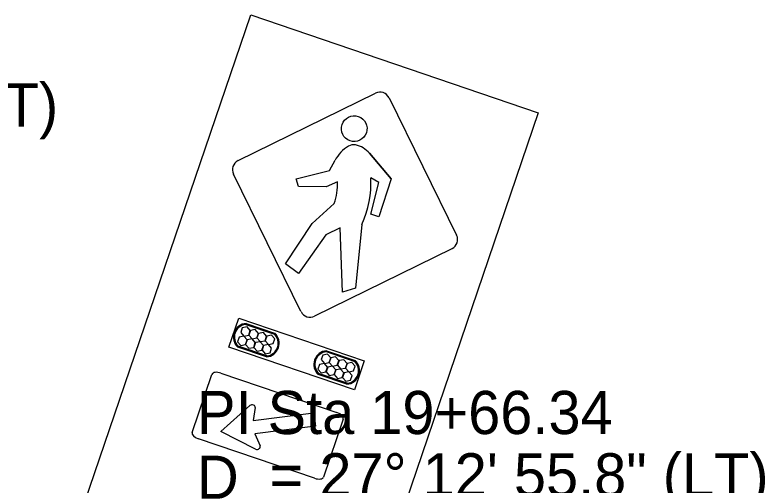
# Model space of a CAD drawing. Extents: x 902965 to 1126554, y 597041 to 686906.
# Drawn here: x 928783.5 to 928905.1, y 686035.7 to 686112 of the extents above; entities that cross this region are included whole.
import ezdxf

# ---------------------------------------------------------------- set-up
doc = ezdxf.new("R2010")
doc.units = 0
for name, color, linetype in [('CTL North Arrow CELL', 7, 'Continuous'), ('Default', 7, 'Continuous'), ('Exist Horizontal Alignment Curve and Spiral Data', 7, 'Continuous'), ('Exist Utilities Water Meter CELL', 7, 'Continuous'), ('WS W11-2 CELL', 7, 'Continuous'), ('WS W16-7p CELL', 7, 'Continuous')]:
    doc.layers.add(name, color=color, linetype=linetype)

msp = doc.modelspace()

# ---------------------------------------------------------------- linework, layer by layer
at = {"layer": 'CTL North Arrow CELL'}
for p, q in [((928785.5, 686005.71), (928821.71, 686111.98)), ((928821.71, 686111.98), (928868.34, 686096.09)), ((928868.34, 686096.09), (928832.13, 685989.82))]:
    msp.add_line(p, q, dxfattribs=at)
at = {"layer": 'Default'}
for points in [[(928838.54, 686051.18), (928818.17, 686058.12), (928819.77, 686062.81), (928840.13, 686055.87)], [(928821.64, 686060.8), (928821.12, 686061.4), (928820.34, 686061.25), (928820.08, 686060.5), (928820.6, 686059.89), (928821.39, 686060.05)], [(928822.96, 686060.34), (928822.44, 686060.94), (928821.66, 686060.79), (928821.4, 686060.04), (928821.92, 686059.44), (928822.71, 686059.59)], [(928824.29, 686059.89), (928823.76, 686060.49), (928822.98, 686060.34), (928822.72, 686059.59), (928823.25, 686058.99), (928824.03, 686059.14)], [(928821.13, 686059.28), (928820.6, 686059.88), (928819.82, 686059.73), (928819.56, 686058.97), (928820.09, 686058.37), (928820.87, 686058.53)], [(928822.45, 686058.83), (928821.93, 686059.43), (928821.14, 686059.27), (928820.88, 686058.52), (928821.41, 686057.92), (928822.19, 686058.07)], [(928825.61, 686059.45), (928825.09, 686060.05), (928824.31, 686059.9), (928824.05, 686059.14), (928824.57, 686058.54), (928825.36, 686058.7)], [(928823.77, 686058.38), (928823.25, 686058.98), (928822.47, 686058.83), (928822.21, 686058.07), (928822.73, 686057.47), (928823.52, 686057.63)], [(928825.1, 686057.93), (928824.58, 686058.53), (928823.8, 686058.38), (928823.54, 686057.62), (928824.06, 686057.02), (928824.84, 686057.18)], [(928834.69, 686056.37), (928834.16, 686056.97), (928833.38, 686056.82), (928833.12, 686056.07), (928833.65, 686055.46), (928834.43, 686055.62)], [(928836.01, 686055.91), (928835.48, 686056.51), (928834.7, 686056.36), (928834.44, 686055.61), (928834.97, 686055.01), (928835.75, 686055.16)], [(928837.33, 686055.46), (928836.81, 686056.06), (928836.03, 686055.91), (928835.77, 686055.16), (928836.29, 686054.56), (928837.07, 686054.71)], [(928838.66, 686055.02), (928838.13, 686055.62), (928837.35, 686055.47), (928837.09, 686054.71), (928837.62, 686054.11), (928838.4, 686054.27)], [(928834.17, 686054.85), (928833.65, 686055.45), (928832.86, 686055.3), (928832.61, 686054.54), (928833.13, 686053.94), (928833.91, 686054.1)], [(928835.49, 686054.4), (928834.97, 686055), (928834.19, 686054.85), (928833.93, 686054.09), (928834.45, 686053.49), (928835.23, 686053.64)], [(928836.82, 686053.95), (928836.29, 686054.55), (928835.51, 686054.4), (928835.25, 686053.65), (928835.78, 686053.04), (928836.56, 686053.2)], [(928838.15, 686053.5), (928837.62, 686054.1), (928836.84, 686053.95), (928836.58, 686053.19), (928837.11, 686052.59), (928837.89, 686052.75)]]:
    msp.add_lwpolyline(points, close=True, dxfattribs=at)
at = {"layer": 'Exist Utilities Water Meter CELL'}
for p, q in [((928822.62, 686059.23), (928822.62, 686059.23)), ((928835.66, 686054.8), (928835.66, 686054.8))]:
    msp.add_line(p, q, dxfattribs=at)
for points in [[(928820.91, 686061.8), (928825.54, 686060.22)], [(928820.96, 686061.95), (928825.59, 686060.38)], [(928824.27, 686056.51), (928819.62, 686058.1)], [(928824.33, 686056.67), (928819.67, 686058.26)], [(928833.95, 686057.37), (928838.58, 686055.79)], [(928834, 686057.52), (928838.63, 686055.95)], [(928837.32, 686052.08), (928832.66, 686053.67)], [(928837.37, 686052.24), (928832.71, 686053.83)]]:
    msp.add_lwpolyline(points, dxfattribs=at)
for centre, radius, start, end in [((928821.13, 686059.73), 2.23, 94.3617, 227.1631), ((928821.14, 686059.73), 2.08, 96.4846, 224.9661), ((928824.09, 686058.73), 2.23, 274.832, 47.4921), ((928824.1, 686058.73), 2.07, 276.3109, 46.0565), ((928834.17, 686055.3), 2.23, 94.3617, 227.1631), ((928834.19, 686055.3), 2.08, 96.4846, 224.9661), ((928837.13, 686054.3), 2.23, 274.832, 47.4921), ((928837.14, 686054.3), 2.07, 276.3109, 46.0565)]:
    msp.add_arc(centre, radius, start, end, dxfattribs=at)
at = {"layer": 'WS W11-2 CELL'}
for p, q in [((928834.5, 686086.77), (928835.39, 686088.41)), ((928840.98, 686089.55), (928844.51, 686085.39)), ((928844.51, 686085.39), (928840.98, 686089.55)), ((928840.98, 686089.55), (928844.51, 686085.39)), ((928829.1, 686085.38), (928834.5, 686086.77)), ((928829.46, 686084.17), (928829.1, 686085.38)), ((928835.78, 686084.92), (928833.97, 686084.12)), ((928842.51, 686084.79), (928841.17, 686085.57)), ((928841.21, 686079.65), (928842.51, 686084.79)), ((928844.51, 686085.39), (928842.47, 686079.22)), ((928833.97, 686084.12), (928829.46, 686084.17)), ((928831.7, 686078.14), (928835.26, 686081.42)), ((928842.47, 686079.22), (928841.21, 686079.65)), ((928827.36, 686071.59), (928831.7, 686078.14)), ((928839.72, 686078.02), (928838.72, 686067.66)), ((928833.9, 686076.3), (928829.46, 686070.04)), ((928836.22, 686077.43), (928833.9, 686076.3)), ((928836.59, 686067.04), (928836.22, 686077.43)), ((928854.35, 686074.07), (928832.06, 686063.11)), ((928854.35, 686074.07), (928832.06, 686063.11)), ((928829.46, 686070.04), (928827.36, 686071.59)), ((928838.72, 686067.66), (928836.59, 686067.04))]:
    msp.add_line(p, q, dxfattribs=at)
for points in [[(928819.65, 686088.35), (928841.94, 686099.31)], [(928844.14, 686098.56), (928855.1, 686076.27)], [(928829.86, 686063.86), (928818.9, 686086.15)]]:
    msp.add_lwpolyline(points, dxfattribs=at)
for centre, major_axis, start_param, end_param in [((928842.67, 686097.84), (0.53, 1.55), 6.283072, 7.068583), ((928842.67, 686097.84), (0.53, 1.55), 5.49756, 6.283072), ((928838.38, 686089.36), (-0.51, -1.49), 3.261682, 4.017186), ((928837.86, 686086.89), (1.32, 3.88), 5.744678, 6.403274), ((928840.7, 686085.56), (-1.95, -5.71), 4.017186, 4.547553), ((928820.37, 686086.88), (0.53, 1.55), 0.785398, 2.356194), ((928825.65, 686084.64), (3.27, 9.6), 4.717416, 5.067864), ((928825.65, 686084.64), (5.02, 14.72), 4.60131, 5.100443), ((928853.63, 686075.55), (0.53, 1.55), 3.926991, 5.497787), ((928831.34, 686064.58), (-0.53, -1.55), 5.497787, 6.283185), ((928831.34, 686064.58), (-0.53, -1.55), 6.283185, 7.068583)]:
    msp.add_ellipse(centre, major_axis=major_axis, ratio=0.999996, start_param=start_param, end_param=end_param, dxfattribs=at)
msp.add_ellipse((928838.49, 686093.54), major_axis=(0.67, 1.97), ratio=0.999996, dxfattribs=at)
at = {"layer": 'WS W16-7p CELL'}
for p, q in [((928816.87, 686044.42), (928821.56, 686048.63)), ((928822.42, 686048.31), (928822.1, 686046.18)), ((928822.1, 686046.18), (928831.92, 686047.45)), ((928831.92, 686047.45), (928832.2, 686045.3)), ((928832.2, 686045.3), (928822.38, 686044.03)), ((928822.47, 686041.55), (928816.87, 686044.42)), ((928822.38, 686044.03), (928823.22, 686042.08)), ((928822.65, 686040.03), (928813.24, 686043.24)), ((928832.05, 686036.83), (928822.65, 686040.03))]:
    msp.add_line(p, q, dxfattribs=at)
for points in [[(928812.21, 686044.28), (928815.42, 686053.69)], [(928816.87, 686053.89), (928826.28, 686050.68)], [(928826.28, 686050.68), (928835.68, 686047.48)], [(928836.71, 686046.43), (928833.51, 686037.03)]]:
    msp.add_lwpolyline(points, dxfattribs=at)
for centre, major_axis, ratio, start_param, end_param in [((928816.66, 686053.27), (-1.24, 0.42), 0.5, 4.712162, 6.283185), ((928821.9, 686048.36), (-0.53, -0.069), 0.720018, 2.830617, 5.313577), ((928835.47, 686046.86), (1.24, -0.42), 0.5, 0, 1.570796), ((928813.45, 686043.86), (-1.24, 0.42), 0.5, 0, 1.570796), ((928822.73, 686041.9), (-0.53, -0.069), 0.720018, 0.96961, 3.452569), ((928832.27, 686037.45), (-1.24, 0.42), 0.5, 1.570796, 3.141593)]:
    msp.add_ellipse(centre, major_axis=major_axis, ratio=ratio, start_param=start_param, end_param=end_param, dxfattribs=at)

# ---------------------------------------------------------------- texts
at = {"layer": 'Exist Horizontal Alignment Curve and Spiral Data'}
for s, p in [('= 5%%d 55\' 30.8" (LT)', (928714.77, 686093.89)), ('PI Sta 19+66.34', (928813, 686044)), ('= 27%%d 12\' 55.8" (LT)', (928824.77, 686033.89)), ('D', (928813, 686033.5))]:
    msp.add_text(s, height=7, dxfattribs=at).set_placement(p)

doc.saveas('drawing.dxf')
